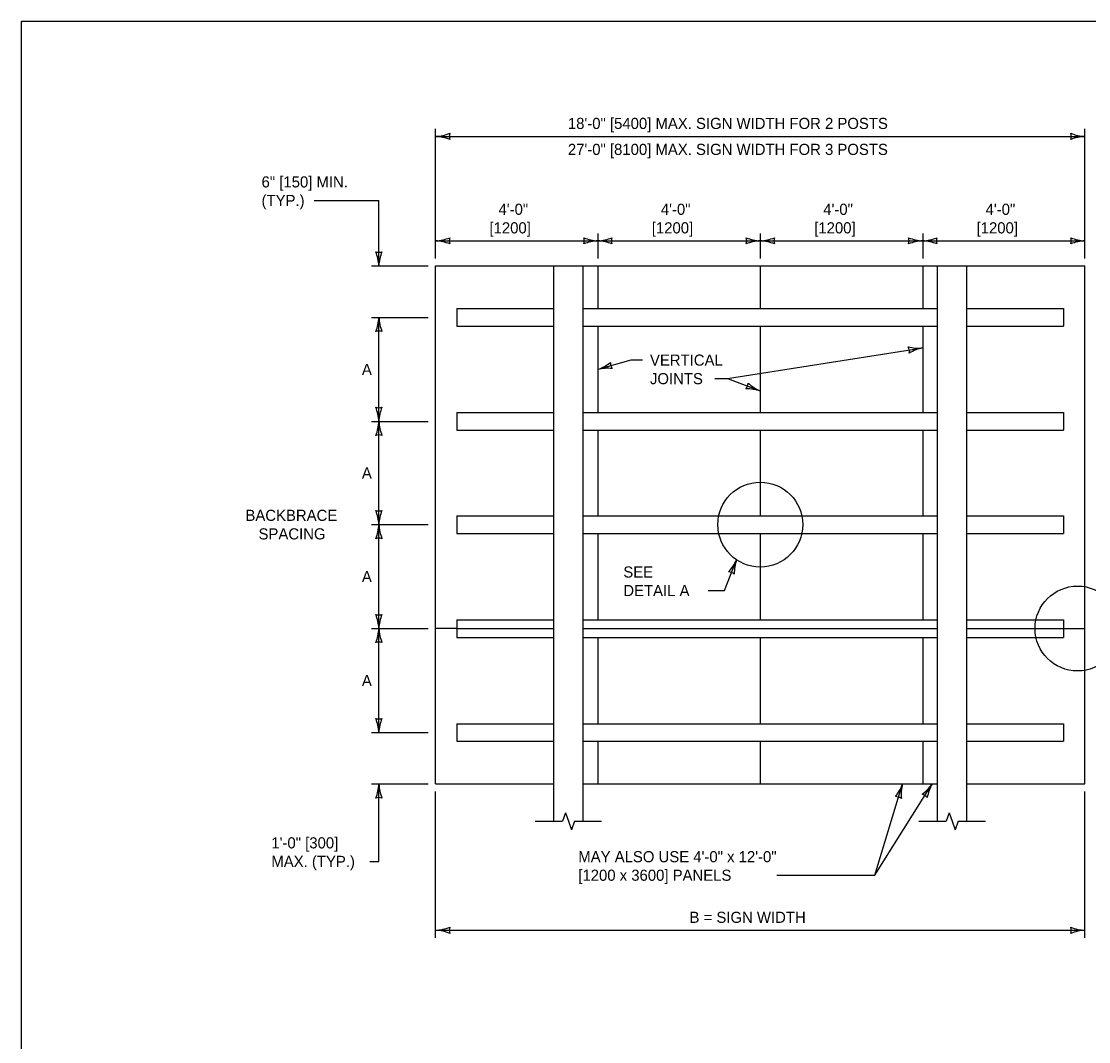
# Model space of a CAD drawing. Extents: x 49991.4 to 50021, y 49987.6 to 50011.4.
# Drawn here: x 49999.38 to 50005.14, y 49993.5 to 49999 of the extents above; entities that cross this region are included whole.
import ezdxf

# ---------------------------------------------------------------- set-up
doc = ezdxf.new("R2010")
doc.units = 0
for name, color, linetype in [('Level 1', 7, 'Continuous'), ('Level 2', 7, 'Continuous'), ('Level 3', 7, 'Continuous'), ('Level 4', 7, 'Continuous'), ('Level 6', 7, 'Continuous')]:
    doc.layers.add(name, color=color, linetype=linetype)

msp = doc.modelspace()

# ---------------------------------------------------------------- linework, layer by layer
at = {"layer": 'Level 1'}
for p, q in [((50001.6162, 49997.6802), (50005.1157, 49997.6802)), ((50001.6162, 49994.886), (50001.6162, 49997.6802)), ((50002.2526, 49996.6696), (50002.2526, 49997.6802)), ((50002.4109, 49996.6696), (50002.4109, 49997.6802)), ((50002.4906, 49997.6802), (50002.4906, 49997.4499)), ((50003.366, 49997.6802), (50003.366, 49997.4499)), ((50004.2414, 49997.6802), (50004.2414, 49997.4499)), ((50004.3209, 49996.6696), (50004.3209, 49997.6802)), ((50004.4793, 49996.6696), (50004.4793, 49997.6802)), ((50005.1157, 49994.886), (50005.1157, 49997.6802)), ((50001.7306, 49997.4499), (50002.2526, 49997.4499)), ((50001.7306, 49997.4499), (50001.7306, 49997.3548)), ((50002.4109, 49997.4499), (50004.3209, 49997.4499)), ((50004.4793, 49997.4499), (50005.001, 49997.4499)), ((50005.001, 49997.4499), (50005.001, 49997.3548)), ((50001.7306, 49997.3548), (50002.2526, 49997.3548)), ((50002.4109, 49997.3548), (50004.3209, 49997.3548)), ((50002.4906, 49997.3548), (50002.4906, 49996.8893)), ((50003.366, 49997.3548), (50003.366, 49996.8893)), ((50004.2414, 49997.3548), (50004.2414, 49996.8893)), ((50004.4793, 49997.3548), (50005.001, 49997.3548)), ((50001.7306, 49996.8893), (50002.2526, 49996.8893)), ((50001.7306, 49996.8893), (50001.7306, 49996.7941)), ((50002.4109, 49996.8893), (50004.3209, 49996.8893)), ((50004.4793, 49996.8893), (50005.001, 49996.8893)), ((50005.001, 49996.8893), (50005.001, 49996.7941)), ((50001.7306, 49996.7941), (50002.2526, 49996.7941)), ((50002.4109, 49996.7941), (50004.3209, 49996.7941)), ((50002.4906, 49996.7941), (50002.4906, 49996.3326)), ((50003.366, 49996.7941), (50003.366, 49996.3326)), ((50004.2414, 49996.7941), (50004.2414, 49996.3326)), ((50004.3184, 49996.7941), (50004.3204, 49996.7941)), ((50004.4793, 49996.7941), (50005.001, 49996.7941)), ((50002.2526, 49994.6852), (50002.2526, 49996.6696)), ((50002.4109, 49994.6852), (50002.4109, 49996.6696)), ((50004.3209, 49994.6852), (50004.3209, 49996.6696)), ((50004.4793, 49994.6852), (50004.4793, 49996.6696)), ((50001.7306, 49996.3326), (50002.2526, 49996.3326)), ((50001.7306, 49996.3326), (50001.7306, 49996.2374)), ((50002.4109, 49996.3326), (50004.3209, 49996.3326)), ((50004.3184, 49996.3326), (50004.3204, 49996.3326)), ((50004.4793, 49996.3326), (50005.001, 49996.3326)), ((50005.001, 49996.3326), (50005.001, 49996.2374)), ((50001.7306, 49996.2374), (50002.2526, 49996.2374)), ((50002.4109, 49996.2374), (50004.3209, 49996.2374)), ((50002.4906, 49996.2374), (50002.4906, 49995.7719)), ((50003.366, 49996.2374), (50003.366, 49995.7719)), ((50004.2414, 49996.2374), (50004.2414, 49995.7719)), ((50004.4793, 49996.2374), (50005.001, 49996.2374)), ((50001.7306, 49995.7719), (50002.2526, 49995.7719)), ((50001.7306, 49995.7719), (50001.7306, 49995.6767)), ((50002.4109, 49995.7719), (50004.3209, 49995.7719)), ((50004.3184, 49995.7719), (50004.3204, 49995.7719)), ((50004.4793, 49995.7719), (50005.001, 49995.7719)), ((50005.001, 49995.7719), (50005.001, 49995.6767)), ((50001.7306, 49995.7244), (50001.6162, 49995.7244)), ((50005.0013, 49995.7244), (50005.1157, 49995.7244)), ((50001.7306, 49995.6767), (50002.2526, 49995.6767)), ((50002.4109, 49995.6767), (50004.3209, 49995.6767)), ((50002.4906, 49995.6767), (50002.4906, 49995.2112)), ((50003.366, 49995.6767), (50003.366, 49995.2112)), ((50004.2414, 49995.6767), (50004.2414, 49995.2112)), ((50004.4793, 49995.6767), (50005.001, 49995.6767)), ((50001.7306, 49995.2112), (50002.2526, 49995.2112)), ((50001.7306, 49995.2112), (50001.7306, 49995.1162)), ((50002.4109, 49995.2112), (50004.3209, 49995.2112)), ((50004.4793, 49995.2112), (50005.001, 49995.2112)), ((50005.001, 49995.2112), (50005.001, 49995.1162)), ((50001.7306, 49995.1162), (50002.2526, 49995.1162)), ((50002.4109, 49995.1162), (50004.3209, 49995.1162)), ((50002.4906, 49995.1162), (50002.4906, 49994.886)), ((50003.366, 49995.1162), (50003.366, 49994.886)), ((50004.2414, 49995.1157), (50004.2414, 49994.886)), ((50004.4793, 49995.1162), (50005.001, 49995.1162)), ((50001.6162, 49994.886), (50002.2526, 49994.886)), ((50002.4109, 49994.886), (50004.3209, 49994.886)), ((50004.4793, 49994.886), (50005.1157, 49994.886))]:
    msp.add_line(p, q, dxfattribs=at)
msp.add_lwpolyline([(49999.3835, 49998.9992), (50016.7501, 49998.9992), (50016.7501, 49987.7988), (49999.3835, 49987.7988)], close=True, dxfattribs=at)
at = {"layer": 'Level 3'}
for p, q in [((50001.6162, 49997.7202), (50001.6162, 49998.4186)), ((50005.1157, 49997.7202), (50005.1157, 49998.4186)), ((50001.6162, 49998.3786), (50005.1157, 49998.3786)), ((50000.9618, 49998.0332), (50001.3104, 49998.0332)), ((50001.3104, 49997.6802), (50001.3104, 49998.0332)), ((50002.4906, 49997.8555), (50002.4906, 49997.7202)), ((50003.366, 49997.8555), (50003.366, 49997.7202)), ((50004.2414, 49997.8555), (50004.2414, 49997.7202)), ((50001.6162, 49997.8155), (50002.4906, 49997.8155)), ((50002.4906, 49997.8155), (50003.366, 49997.8155)), ((50003.366, 49997.8155), (50004.2414, 49997.8155)), ((50004.2414, 49997.8155), (50005.1157, 49997.8155)), ((50001.2704, 49997.6802), (50001.5762, 49997.6802)), ((50001.2704, 49997.4024), (50001.5762, 49997.4024)), ((50001.3104, 49996.8417), (50001.3104, 49997.4024)), ((50003.1886, 49997.0721), (50004.2414, 49997.2384)), ((50002.6678, 49997.1721), (50002.4906, 49997.1221)), ((50002.7314, 49997.1721), (50002.6678, 49997.1721)), ((50003.1204, 49997.0721), (50003.1886, 49997.0721)), ((50003.1886, 49997.0721), (50003.366, 49997.0057)), ((50001.2704, 49996.8417), (50001.5762, 49996.8417)), ((50001.3104, 49996.285), (50001.3104, 49996.8417)), ((50001.2704, 49996.285), (50001.5762, 49996.285)), ((50001.3104, 49995.7244), (50001.3104, 49996.285)), ((50003.1728, 49995.9293), (50003.2382, 49996.0951)), ((50003.0844, 49995.9293), (50003.1728, 49995.9293)), ((50001.2704, 49995.7244), (50001.5762, 49995.7244)), ((50001.3104, 49995.1637), (50001.3104, 49995.7244)), ((50001.2704, 49995.1637), (50001.5762, 49995.1637)), ((50001.2704, 49994.886), (50001.5762, 49994.886)), ((50001.3104, 49994.4686), (50001.3104, 49994.886)), ((50001.6162, 49994.057), (50001.6162, 49994.846)), ((50003.9832, 49994.394), (50004.1322, 49994.886)), ((50003.9832, 49994.394), (50004.2923, 49994.886)), ((50005.1157, 49994.057), (50005.1157, 49994.846)), ((50001.2618, 49994.4686), (50001.3104, 49994.4686)), ((50003.4555, 49994.394), (50003.9832, 49994.394)), ((50001.6162, 49994.097), (50005.1157, 49994.097))]:
    msp.add_line(p, q, dxfattribs=at)
for centre in [(50003.3659, 49996.285), (50005.0758, 49995.7244)]:
    msp.add_circle(centre, 0.2289, dxfattribs=at)
for centre, radius, start, end in [((50001.6047, 49998.6113), 0.233, 272.82731, 292.07716), ((50001.607, 49998.1564), 0.2223, 67.45601, 87.63952), ((50001.7444, 49998.3786), 0.0548, 162.13882, 197.86118), ((50005.1249, 49998.6007), 0.2223, 247.45601, 267.63952), ((50004.9875, 49998.3786), 0.0548, 342.13882, 17.86118), ((50005.1272, 49998.1459), 0.233, 92.82731, 112.07716), ((50001.6047, 49998.0482), 0.233, 272.82731, 292.07716), ((50001.607, 49997.5934), 0.2223, 67.45601, 87.63952), ((50001.7444, 49997.8155), 0.0548, 162.13882, 197.86118), ((50002.4998, 49998.0376), 0.2223, 247.45601, 267.63952), ((50002.3624, 49997.8155), 0.0548, 342.13882, 17.86118), ((50002.5021, 49997.5828), 0.233, 92.82731, 112.07716), ((50002.4791, 49998.0482), 0.233, 272.82731, 292.07716), ((50002.4814, 49997.5934), 0.2223, 67.45601, 87.63952), ((50002.6188, 49997.8155), 0.0548, 162.13882, 197.86118), ((50003.3752, 49998.0376), 0.2223, 247.45601, 267.63952), ((50003.2378, 49997.8155), 0.0548, 342.13882, 17.86118), ((50003.3775, 49997.5828), 0.233, 92.82731, 112.07716), ((50003.3545, 49998.0482), 0.233, 272.82731, 292.07716), ((50003.3568, 49997.5934), 0.2223, 67.45601, 87.63952), ((50003.4942, 49997.8155), 0.0548, 162.13882, 197.86118), ((50004.2506, 49998.0376), 0.2223, 247.45601, 267.63952), ((50004.1132, 49997.8155), 0.0548, 342.13882, 17.86118), ((50004.2529, 49997.5828), 0.233, 92.82731, 112.07716), ((50004.2299, 49998.0482), 0.233, 272.82731, 292.07716), ((50004.2322, 49997.5934), 0.2223, 67.45601, 87.63952), ((50004.3696, 49997.8155), 0.0548, 162.13882, 197.86118), ((50005.1249, 49998.0376), 0.2223, 247.45601, 267.63952), ((50004.9875, 49997.8155), 0.0548, 342.13882, 17.86118), ((50005.1272, 49997.5828), 0.233, 92.82731, 112.07716), ((50001.3104, 49997.8084), 0.0548, 252.13882, 287.86118), ((50001.0777, 49997.6687), 0.233, 2.82731, 22.07716), ((50001.5325, 49997.671), 0.2223, 157.45601, 177.63952), ((50001.0883, 49997.4115), 0.2223, 337.45601, 357.63952), ((50001.5431, 49997.4138), 0.233, 182.82731, 202.07716), ((50001.3104, 49997.2741), 0.0548, 72.13882, 107.86118), ((50004.2158, 49997.4592), 0.2223, 256.43492, 276.61843), ((50004.1148, 49997.2184), 0.0548, 351.11773, 26.84009), ((50004.2891, 49997.0103), 0.233, 101.80622, 121.05607), ((50002.4164, 49997.3429), 0.233, 288.58463, 307.83448), ((50002.614, 49997.1569), 0.0548, 177.89614, 213.6185), ((50002.5421, 49996.9058), 0.2223, 83.21333, 103.39684), ((50003.2459, 49997.0506), 0.0548, 321.63234, 357.3547), ((50003.4524, 49997.2105), 0.2223, 226.94953, 247.13304), ((50003.2952, 49996.7837), 0.233, 72.32083, 91.57068), ((50001.3104, 49996.9699), 0.0548, 252.13882, 287.86118), ((50001.0777, 49996.8302), 0.233, 2.82731, 22.07716), ((50001.5325, 49996.8325), 0.2223, 157.45601, 177.63952), ((50001.0883, 49996.8509), 0.2223, 337.45601, 357.63952), ((50001.5431, 49996.8532), 0.233, 182.82731, 202.07716), ((50001.3104, 49996.7135), 0.0548, 72.13882, 107.86118), ((50001.3104, 49996.4132), 0.0548, 252.13882, 287.86118), ((50001.0777, 49996.2735), 0.233, 2.82731, 22.07716), ((50001.5325, 49996.2758), 0.2223, 157.45601, 177.63952), ((50001.0883, 49996.2942), 0.2223, 337.45601, 357.63952), ((50001.5431, 49996.2965), 0.233, 182.82731, 202.07716), ((50001.3104, 49996.1568), 0.0548, 72.13882, 107.86118), ((50003.0349, 49996.1851), 0.2223, 315.93569, 336.11919), ((50003.4589, 49996.0204), 0.233, 161.30699, 180.55684), ((50003.1912, 49995.9758), 0.0548, 50.61849, 86.34086), ((50001.3104, 49995.8526), 0.0548, 252.13882, 287.86118), ((50001.0777, 49995.7129), 0.233, 2.82731, 22.07716), ((50001.5325, 49995.7152), 0.2223, 157.45601, 177.63952), ((50001.0883, 49995.7336), 0.2223, 337.45601, 357.63952), ((50001.5431, 49995.7359), 0.233, 182.82731, 202.07716), ((50001.3104, 49995.5962), 0.0548, 72.13882, 107.86118), ((50001.3104, 49995.2919), 0.0548, 252.13882, 287.86118), ((50001.0777, 49995.1522), 0.233, 2.82731, 22.07716), ((50001.5325, 49995.1545), 0.2223, 157.45601, 177.63952), ((50001.0883, 49994.8952), 0.2223, 337.45601, 357.63952), ((50001.5431, 49994.8975), 0.233, 182.82731, 202.07716), ((50003.9223, 49994.9591), 0.2223, 320.60853, 340.79203), ((50004.3583, 49994.8296), 0.233, 165.97983, 185.22968), ((50004.1091, 49995.0119), 0.2223, 305.31881, 325.50232), ((50004.4955, 49994.7719), 0.233, 150.69011, 169.93996), ((50001.3104, 49994.7578), 0.0548, 72.13882, 107.86118), ((50004.095, 49994.7633), 0.0548, 55.29133, 91.0137), ((50004.2241, 49994.7774), 0.0548, 40.00162, 75.72398), ((50001.6047, 49994.3297), 0.233, 272.82731, 292.07716), ((50001.607, 49993.8749), 0.2223, 67.45601, 87.63952), ((50001.7444, 49994.097), 0.0548, 162.13882, 197.86118), ((50005.1249, 49994.3191), 0.2223, 247.45601, 267.63952), ((50004.9875, 49994.097), 0.0548, 342.13882, 17.86118), ((50005.1272, 49993.8643), 0.233, 92.82731, 112.07716)]:
    msp.add_arc(centre, radius, start, end, dxfattribs=at)
at = {"layer": 'Level 4'}
for p, q in [((50001.7306, 49995.7244), (50002.2526, 49995.7244)), ((50002.4109, 49995.7244), (50004.3209, 49995.7244)), ((50004.4793, 49995.7244), (50005.0013, 49995.7244))]:
    msp.add_line(p, q, dxfattribs=at)
at = {"layer": 'Level 6'}
for p, q in [((50002.3155, 49994.7309), (50002.2993, 49994.6852)), ((50002.3155, 49994.7309), (50002.3317, 49994.6852)), ((50004.3838, 49994.7309), (50004.3676, 49994.6852)), ((50004.3838, 49994.7309), (50004.4, 49994.6852)), ((50002.1526, 49994.6852), (50002.2993, 49994.6852)), ((50002.3317, 49994.6852), (50002.3479, 49994.6395)), ((50002.3641, 49994.6852), (50002.3479, 49994.6395)), ((50002.3641, 49994.6852), (50002.5109, 49994.6852)), ((50004.2209, 49994.6852), (50004.3676, 49994.6852)), ((50004.4, 49994.6852), (50004.4162, 49994.6395)), ((50004.4324, 49994.6852), (50004.4162, 49994.6395)), ((50004.4324, 49994.6852), (50004.5793, 49994.6852))]:
    msp.add_line(p, q, dxfattribs=at)

# ---------------------------------------------------------------- texts
at = {"layer": 'Level 2'}
for s, p in [('18\'-0" [5400] MAX. SIGN WIDTH FOR 2 POSTS', (50002.329, 49998.4186)), ('27\'-0" [8100] MAX. SIGN WIDTH FOR 3 POSTS', (50002.329, 49998.2786)), ('6" [150] MIN.', (50000.6781, 49998.1032)), ('(TYP.)', (50000.6781, 49998.0032)), ('4\'-0"', (50001.9551, 49997.9555)), ('4\'-0"', (50002.83, 49997.9555)), ('4\'-0"', (50003.7054, 49997.9555)), ('4\'-0"', (50004.5803, 49997.9555)), ('[1200]', (50001.9064, 49997.8555)), ('[1200]', (50002.7813, 49997.8555)), ('[1200]', (50003.6567, 49997.8555)), ('[1200]', (50004.5316, 49997.8555)), ('VERTICAL', (50002.7714, 49997.1421)), ('A', (50001.2189, 49997.092)), ('JOINTS', (50002.7714, 49997.0421)), ('A', (50001.2189, 49996.5334)), ('BACKBRACE', (50000.5913, 49996.305)), ('SPACING', (50000.6619, 49996.205)), ('SEE', (50002.6278, 49995.9993)), ('A', (50001.2189, 49995.9747)), ('DETAIL A', (50002.6278, 49995.8993)), ('A', (50001.2189, 49995.414)), ('1\'-0" [300]', (50000.731, 49994.5386)), ('MAX. (TYP.)', (50000.731, 49994.4386)), ('MAY ALSO USE 4\'-0" x 12\'-0"', (50002.3852, 49994.464)), ('[1200 x 3600] PANELS', (50002.3852, 49994.364)), ('B = SIGN WIDTH', (50002.9845, 49994.137))]:
    msp.add_text(s, height=0.06, dxfattribs=at).set_placement(p)

doc.saveas('drawing.dxf')
